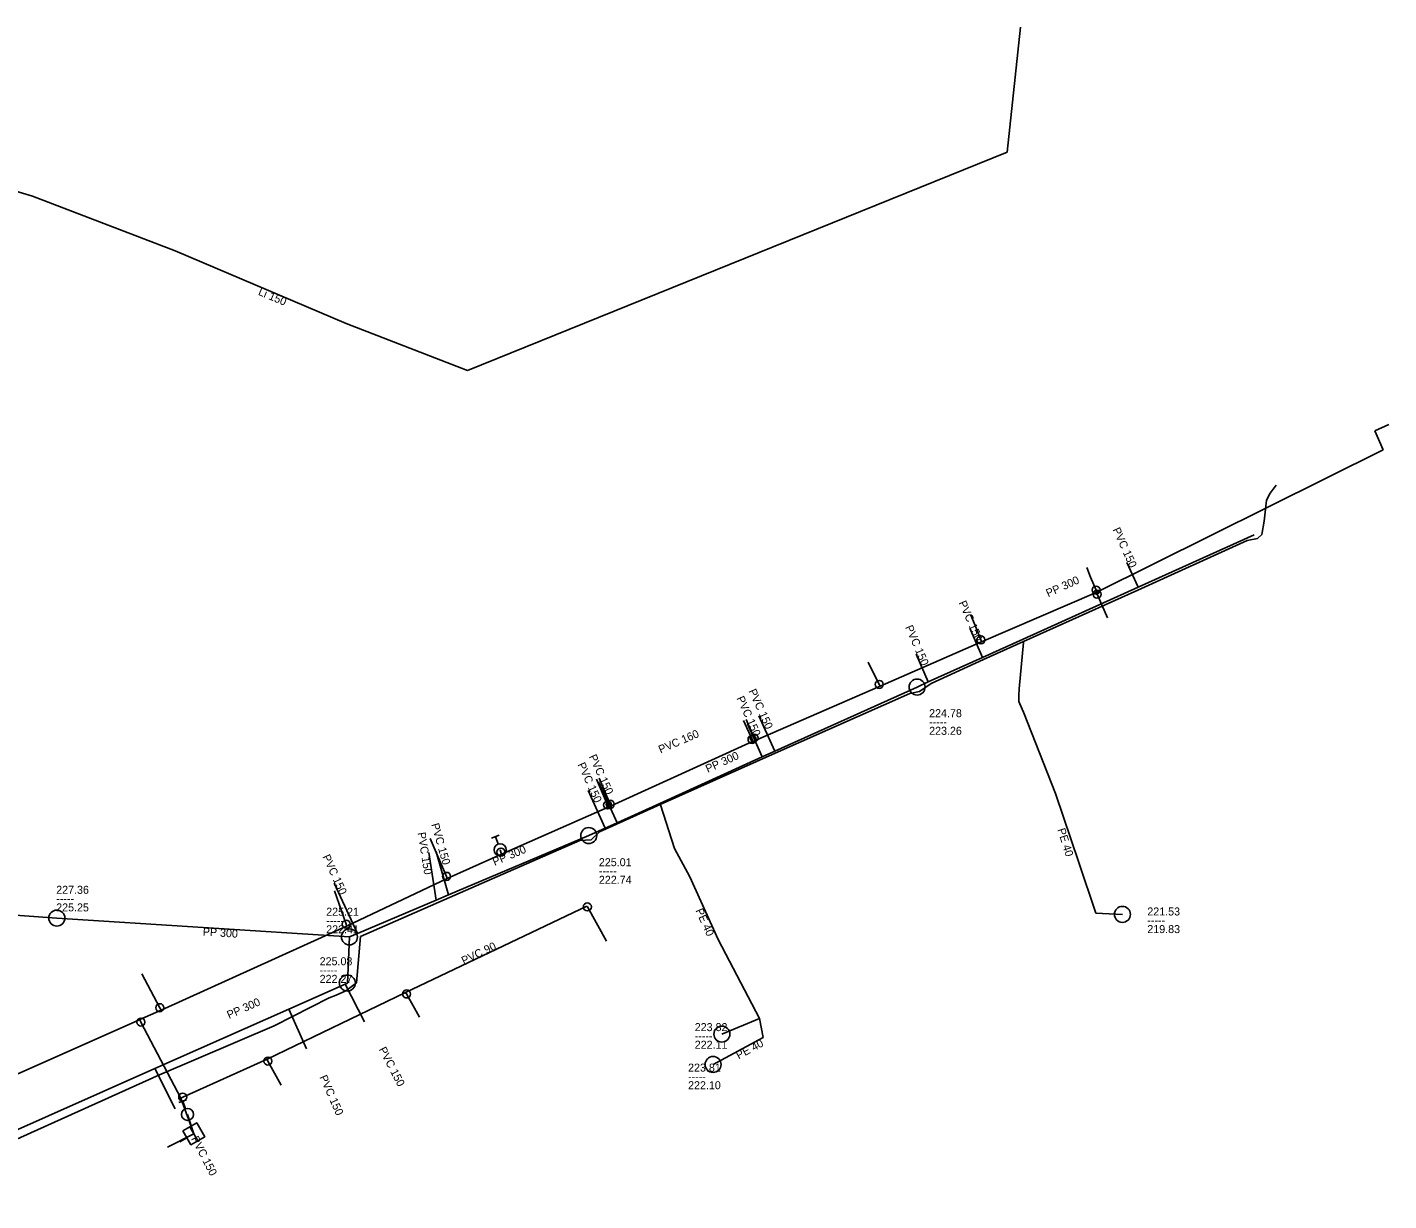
# Model space of a CAD drawing. Extents: x -770828 to -770111, y -1050344 to -1049447.
# Drawn here: x -770280.9 to -770110.7, y -1050279.7 to -1050133.1 of the extents above; entities that cross this region are included whole.
import ezdxf

# ---------------------------------------------------------------- set-up
doc = ezdxf.new("R2010")
doc.units = 0
doc.layers.add('Level 0', color=7, linetype='Continuous')

msp = doc.modelspace()

# ---------------------------------------------------------------- linework, layer by layer
at = {"layer": 'Level 0'}
for p, q in [((-770156.74, -1050133.07), (-770158.4, -1050148.69)), ((-770158.4, -1050148.69), (-770225.84, -1050175.95)), ((-770280.22, -1050154.16), (-770291.37, -1050150.94)), ((-770262.4, -1050161.03), (-770280.22, -1050154.16)), ((-770241, -1050170.09), (-770262.4, -1050161.03)), ((-770225.84, -1050175.95), (-770241, -1050170.09)), ((-770110.7, -1050182.71), (-770112.46, -1050183.49)), ((-770112.46, -1050183.49), (-770111.4, -1050185.86)), ((-770111.4, -1050185.86), (-770147.26, -1050203.69)), ((-770125.54, -1050191.28), (-770124.79, -1050190.31)), ((-770126.27, -1050194.78), (-770125.97, -1050192.16)), ((-770125.97, -1050192.16), (-770125.54, -1050191.28)), ((-770126.55, -1050196.47), (-770126.27, -1050194.78)), ((-770142.08, -1050203.41), (-770128.41, -1050197.21)), ((-770127.54, -1050196.49), (-770142.03, -1050203.03)), ((-770128.41, -1050197.21), (-770127.12, -1050196.98)), ((-770127.12, -1050196.98), (-770126.55, -1050196.47)), ((-770147.98, -1050201.79), (-770148.45, -1050200.58)), ((-770142.03, -1050203.03), (-770143.43, -1050199.94)), ((-770147.29, -1050203.4), (-770147.98, -1050201.79)), ((-770147.26, -1050203.69), (-770161.61, -1050209.87)), ((-770142.03, -1050203.03), (-770156.38, -1050209.52)), ((-770156.37, -1050209.83), (-770142.08, -1050203.41)), ((-770147.26, -1050203.69), (-770147.29, -1050203.4)), ((-770147.16, -1050203.93), (-770147.26, -1050203.69)), ((-770145.86, -1050206.88), (-770147.16, -1050203.93)), ((-770162.4, -1050207.82), (-770162.93, -1050206.55)), ((-770161.67, -1050209.63), (-770162.4, -1050207.82)), ((-770161.46, -1050211.82), (-770163.07, -1050208.17)), ((-770161.61, -1050209.87), (-770161.67, -1050209.63)), ((-770156.38, -1050209.52), (-770161.46, -1050211.82)), ((-770161.61, -1050209.87), (-770174.28, -1050215.42)), ((-770168.27, -1050214.89), (-770169.77, -1050211.4)), ((-770161.37, -1050212.07), (-770156.37, -1050209.83)), ((-770156.37, -1050209.95), (-770156.88, -1050215.75)), ((-770156.37, -1050209.83), (-770156.37, -1050209.95)), ((-770174.39, -1050215.19), (-770175.76, -1050212.42)), ((-770161.46, -1050211.82), (-770168.27, -1050214.89)), ((-770167.9, -1050215.07), (-770161.37, -1050212.07)), ((-770174.28, -1050215.42), (-770189.9, -1050222.19)), ((-770169.65, -1050215.52), (-770187.43, -1050223.55)), ((-770187.39, -1050223.79), (-770170.55, -1050216.34)), ((-770174.28, -1050215.42), (-770174.39, -1050215.19)), ((-770170.55, -1050216.34), (-770169.36, -1050216.1)), ((-770168.27, -1050214.89), (-770169.65, -1050215.52)), ((-770169.36, -1050216.1), (-770167.9, -1050215.07)), ((-770156.88, -1050215.75), (-770156.93, -1050216.57)), ((-770156.93, -1050216.57), (-770156.94, -1050217.33)), ((-770156.94, -1050217.33), (-770156.54, -1050218.3)), ((-770190.29, -1050222.06), (-770191.37, -1050219.72)), ((-770190.02, -1050221.91), (-770191.04, -1050219.58)), ((-770187.43, -1050223.55), (-770189.42, -1050219.14)), ((-770156.54, -1050218.3), (-770156.36, -1050218.65)), ((-770156.36, -1050218.65), (-770152.34, -1050228.81)), ((-770189, -1050224.26), (-770190.86, -1050220.13)), ((-770190.21, -1050222.32), (-770207.91, -1050230.38)), ((-770190.21, -1050222.32), (-770190.29, -1050222.06)), ((-770189.9, -1050222.19), (-770190.21, -1050222.32)), ((-770189.9, -1050222.19), (-770190.02, -1050221.91)), ((-770189, -1050224.26), (-770201.82, -1050230.07)), ((-770201.75, -1050230.22), (-770187.39, -1050223.79)), ((-770187.43, -1050223.55), (-770189, -1050224.26)), ((-770208.35, -1050230.26), (-770209.71, -1050227.05)), ((-770207.14, -1050232.48), (-770209.48, -1050227.37)), ((-770208.01, -1050230.18), (-770209.39, -1050226.93)), ((-770208.64, -1050233.15), (-770210.76, -1050228.46)), ((-770201.82, -1050230.07), (-770207.14, -1050232.48)), ((-770152.34, -1050228.81), (-770149.45, -1050237.44)), ((-770208.27, -1050230.54), (-770221.6, -1050236.4)), ((-770209.37, -1050233.63), (-770201.75, -1050230.22)), ((-770208.27, -1050230.54), (-770208.35, -1050230.26)), ((-770207.91, -1050230.38), (-770208.27, -1050230.54)), ((-770207.91, -1050230.38), (-770208.01, -1050230.18)), ((-770201.75, -1050230.22), (-770201.73, -1050230.25)), ((-770201.73, -1050230.25), (-770199.98, -1050235.68)), ((-770208.64, -1050233.15), (-770210.7, -1050234.08)), ((-770207.14, -1050232.48), (-770208.64, -1050233.15)), ((-770228.47, -1050239.18), (-770230.51, -1050234.45)), ((-770210.7, -1050234.08), (-770228.22, -1050241.5)), ((-770228.12, -1050241.82), (-770211.81, -1050234.71)), ((-770222.84, -1050234.39), (-770221.9, -1050234.04)), ((-770222.03, -1050235.16), (-770222.37, -1050234.22)), ((-770211.81, -1050234.71), (-770210.38, -1050234.6)), ((-770210.38, -1050234.6), (-770209.37, -1050233.63)), ((-770229.75, -1050242.15), (-770230.7, -1050236.22)), ((-770228.22, -1050241.5), (-770229.77, -1050236.1)), ((-770221.6, -1050236.4), (-770228.4, -1050239.43)), ((-770221.67, -1050236.14), (-770221.77, -1050235.86)), ((-770221.6, -1050236.4), (-770221.67, -1050236.14)), ((-770199.98, -1050235.68), (-770198.07, -1050239.22)), ((-770149.45, -1050237.44), (-770147.3, -1050243.78)), ((-770239.62, -1050246.33), (-770242.51, -1050240.03)), ((-770228.4, -1050239.43), (-770240.97, -1050245.42)), ((-770228.4, -1050239.43), (-770228.47, -1050239.18)), ((-770198.07, -1050239.22), (-770194.53, -1050247.09)), ((-770328.72, -1050240.89), (-770277.18, -1050244.39)), ((-770241.01, -1050245.16), (-770242.47, -1050241.01)), ((-770239.24, -1050246.7), (-770228.12, -1050241.82)), ((-770228.22, -1050241.5), (-770229.75, -1050242.15)), ((-770229.75, -1050242.15), (-770239.62, -1050246.33)), ((-770210.92, -1050242.9), (-770233.58, -1050253.7)), ((-770210.92, -1050242.9), (-770210.87, -1050242.99)), ((-770210.87, -1050242.99), (-770208.49, -1050247.26)), ((-770277.18, -1050244.39), (-770240.61, -1050246.75)), ((-770240.97, -1050245.42), (-770264.15, -1050255.89)), ((-770240.97, -1050245.42), (-770241.01, -1050245.16)), ((-770147.3, -1050243.78), (-770143.99, -1050243.93)), ((-770240.61, -1050246.75), (-770240.87, -1050252.51)), ((-770239.62, -1050246.33), (-770240.61, -1050246.75)), ((-770239.74, -1050252.48), (-770239.24, -1050246.7)), ((-770194.53, -1050247.09), (-770189.35, -1050256.96)), ((-770264.31, -1050255.59), (-770266.54, -1050251.35)), ((-770233.58, -1050253.7), (-770250.88, -1050262.04)), ((-770241.16, -1050252.64), (-770248.18, -1050255.76)), ((-770242.28, -1050254.02), (-770241.06, -1050253.48)), ((-770240.87, -1050252.51), (-770241.16, -1050252.64)), ((-770241.16, -1050252.64), (-770238.72, -1050257.36)), ((-770241.06, -1050253.48), (-770239.74, -1050252.48)), ((-770233.58, -1050253.7), (-770233.46, -1050253.88)), ((-770233.46, -1050253.88), (-770231.87, -1050256.76)), ((-770264.15, -1050255.89), (-770264.31, -1050255.59)), ((-770250.02, -1050257.87), (-770243.13, -1050254.35)), ((-770243.13, -1050254.35), (-770242.28, -1050254.02)), ((-770267.13, -1050257.23), (-770317.71, -1050279.72)), ((-770266.81, -1050257.08), (-770267.13, -1050257.23)), ((-770264.15, -1050255.89), (-770266.81, -1050257.08)), ((-770266.67, -1050257.4), (-770266.81, -1050257.08)), ((-770248.18, -1050255.76), (-770264.95, -1050263.2)), ((-770248.18, -1050255.76), (-770245.98, -1050260.74)), ((-770189.35, -1050256.96), (-770194.06, -1050258.89)), ((-770189.35, -1050256.96), (-770188.88, -1050259.32)), ((-770261.68, -1050266.88), (-770266.67, -1050257.4)), ((-770264.35, -1050264), (-770250.02, -1050257.87)), ((-770188.88, -1050259.32), (-770195.16, -1050262.69)), ((-770250.88, -1050262.04), (-770261.45, -1050266.76)), ((-770250.88, -1050262.04), (-770250.79, -1050262.27)), ((-770250.79, -1050262.27), (-770249.14, -1050265.28)), ((-770264.95, -1050263.2), (-770286.27, -1050272.66)), ((-770285.81, -1050273.65), (-770264.35, -1050264)), ((-770264.95, -1050263.2), (-770262.38, -1050268.22)), ((-770261.92, -1050267.45), (-770260.98, -1050267.1)), ((-770261.45, -1050266.76), (-770261.68, -1050266.88)), ((-770260.06, -1050271.35), (-770261.68, -1050266.88)), ((-770261.11, -1050268.22), (-770261.45, -1050267.28)), ((-770260.85, -1050268.92), (-770260.06, -1050271.35)), ((-770260.06, -1050271.35), (-770263.35, -1050273.03)), ((-770261.79, -1050272.35), (-770260.93, -1050271.85))]:
    msp.add_line(p, q, dxfattribs=at)
msp.add_lwpolyline([(-770261.43, -1050270.98), (-770260.43, -1050272.72), (-770259.56, -1050272.22), (-770260.56, -1050270.48)], close=True, dxfattribs=at)
msp.add_lwpolyline([(-770260.56, -1050270.48), (-770259.69, -1050269.98), (-770258.69, -1050271.72), (-770259.56, -1050272.22)], dxfattribs=at)
for centre, radius in [((-770147.29, -1050203.4), 0.5), ((-770147.16, -1050203.93), 0.5), ((-770161.67, -1050209.63), 0.5), ((-770174.39, -1050215.19), 0.5), ((-770169.65, -1050215.52), 1), ((-770190.29, -1050222.06), 0.5), ((-770190.02, -1050221.91), 0.5), ((-770208.35, -1050230.26), 0.5), ((-770208.01, -1050230.18), 0.5), ((-770210.7, -1050234.08), 1), ((-770221.77, -1050235.86), 0.75), ((-770221.67, -1050236.14), 0.5), ((-770228.47, -1050239.18), 0.5), ((-770277.18, -1050244.39), 1), ((-770210.87, -1050242.99), 0.5), ((-770143.99, -1050243.93), 1), ((-770241.01, -1050245.16), 0.5), ((-770240.61, -1050246.75), 1), ((-770240.87, -1050252.51), 1), ((-770233.46, -1050253.88), 0.5), ((-770264.31, -1050255.59), 0.5), ((-770266.67, -1050257.4), 0.5), ((-770194.06, -1050258.89), 1), ((-770250.79, -1050262.27), 0.5), ((-770195.16, -1050262.69), 1), ((-770261.45, -1050266.76), 0.5), ((-770260.85, -1050268.92), 0.75)]:
    msp.add_circle(centre, radius, dxfattribs=at)

# ---------------------------------------------------------------- texts
for s, rotation, p in [('Li 150', 337.054, (-770252.09, -1050166.48)), ('PVC 150', 294.374, (-770145.25, -1050195.85)), ('PP 300', 24.359, (-770153.27, -1050204.31)), ('PVC 150', 293.802, (-770164.49, -1050204.99)), ('PVC 150', 293.258, (-770171.17, -1050208.04)), ('PVC 150', 294.287, (-770190.74, -1050216.02)), ('PVC 150', 294.245, (-770192.25, -1050216.92)), ('PVC 160', 23.433, (-770201.72, -1050223.84)), ('PVC 150', 294.324, (-770212.12, -1050225.21)), ('PVC 150', 294.604, (-770210.7, -1050224.21)), ('PP 300', 24.38, (-770195.82, -1050226.25)), ('PVC 150', 286.015, (-770230.4, -1050232.69)), ('PE 40', 287.407, (-770152.13, -1050233.33)), ('PVC 150', 279.102, (-770232.09, -1050233.74)), ('PVC 150', 294.642, (-770244.01, -1050236.72)), ('PP 300', 23.018, (-770222.46, -1050237.88)), ('PE 40', 294.219, (-770197.38, -1050243.45)), ('PP 300', 356.308, (-770258.96, -1050246.57)), ('PVC 90', 25.738, (-770226.31, -1050250.23)), ('PP 300', 23.962, (-770255.65, -1050257.01)), ('PVC 150', 297.337, (-770236.97, -1050260.8)), ('PE 40', 28.219, (-770191.96, -1050262.06)), ('PVC 150', 293.834, (-770244.38, -1050264.27)), ('PVC 150', 297.11, (-770260.42, -1050271.95))]:
    msp.add_text(s, height=1, rotation=rotation, dxfattribs=at).set_placement(p)
for s, p in [('224.78', (-770168.15, -1050219.29)), ('-----', (-770168.15, -1050220.39)), ('223.26', (-770168.15, -1050221.49)), ('225.01', (-770209.43, -1050237.91)), ('-----', (-770209.43, -1050239.01)), ('222.74', (-770209.43, -1050240.11)), ('-----', (-770277.26, -1050242.46)), ('227.36', (-770277.26, -1050241.36)), ('225.25', (-770277.26, -1050243.56)), ('225.21', (-770243.51, -1050244.1)), ('221.53', (-770140.88, -1050244.07)), ('-----', (-770243.51, -1050245.2)), ('222.41', (-770243.51, -1050246.3)), ('-----', (-770140.88, -1050245.17)), ('219.83', (-770140.88, -1050246.27)), ('225.08', (-770244.33, -1050250.29)), ('-----', (-770244.33, -1050251.39)), ('222.27', (-770244.33, -1050252.49)), ('223.82', (-770197.45, -1050258.52)), ('-----', (-770197.45, -1050259.62)), ('222.11', (-770197.45, -1050260.72)), ('223.81', (-770198.28, -1050263.58)), ('-----', (-770198.28, -1050264.68)), ('222.10', (-770198.28, -1050265.78))]:
    msp.add_text(s, height=1, dxfattribs=at).set_placement(p)

doc.saveas('drawing.dxf')
